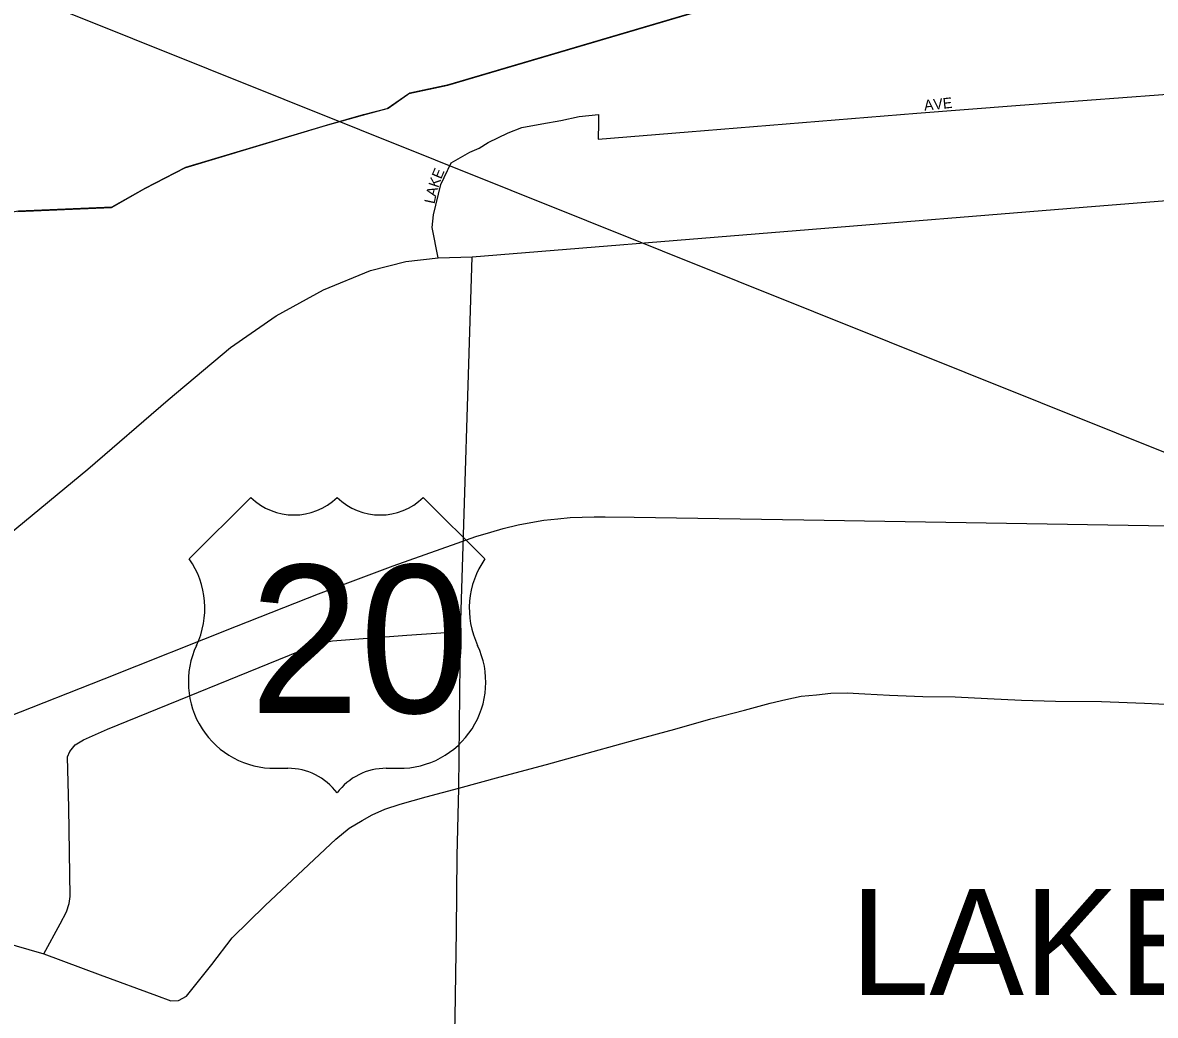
# Model space of a CAD drawing. Extents: x -561 to 1170, y 0 to 846.
# Drawn here: x 141.08 to 155.48, y 270.3 to 282.92 of the extents above; entities that cross this region are included whole.
import ezdxf

# ---------------------------------------------------------------- set-up
doc = ezdxf.new("R2010")
doc.units = 0
for name, color, linetype in [('GM_X_City_Street', 7, 'Continuous'), ('GM_X_City_Street_Text', 7, 'Continuous'), ('GM_X_Corporation_Text', 7, 'Continuous'), ('GM_X_County', 7, 'Continuous'), ('GM_X_Major_Lake', 7, 'Continuous'), ('GM_X_Rail_Line', 7, 'Continuous'), ('GM_X_State_Route', 7, 'Continuous'), ('GM_X_US_Location', 7, 'Continuous'), ('GM_X_US_Route', 7, 'Continuous'), ('GM_X_US_Shield', 7, 'Continuous'), ('SH_Text', 7, 'Continuous')]:
    doc.layers.add(name, color=color, linetype=linetype)

msp = doc.modelspace()

# ---------------------------------------------------------------- linework, layer by layer
at = {"layer": 'GM_X_City_Street'}
for points in [[(148.401, 281.709), (148.4, 281.649), (148.395, 281.44), (149.541, 281.533), (152.447, 281.77), (153.706, 281.868), (158.244, 282.207)], [(146.479, 281.042), (146.488, 281.061), (146.525, 281.139), (146.764, 281.274), (146.883, 281.327), (146.996, 281.397), (147.251, 281.52), (147.424, 281.59), (147.678, 281.638), (147.921, 281.68), (148.154, 281.728), (148.402, 281.754), (148.401, 281.709)], [(146.363, 279.933), (146.284, 280.318), (146.301, 280.48), (146.394, 280.864), (146.479, 281.042)]]:
    msp.add_lwpolyline(points, dxfattribs=at)
at = {"layer": 'GM_X_County'}
msp.add_lwpolyline([(141.015, 280.523), (142.205, 280.574), (142.632, 280.815), (143.139, 281.078), (144.928, 281.614), (145.398, 281.747), (145.712, 281.831), (145.987, 282.022), (146.484, 282.128), (153.359, 284.158)], dxfattribs=at)
at = {"layer": 'GM_X_Major_Lake'}
for points in [[(136.359, 279.012), (137.109, 279.037), (138.946, 279.764), (139.491, 280.049), (139.816, 280.148), (140.151, 280.205), (140.496, 280.445), (141.026, 280.53), (142.217, 280.581), (142.643, 280.822), (143.151, 281.085), (144.94, 281.621), (145.41, 281.754), (145.724, 281.837), (145.999, 282.029), (146.496, 282.135), (153.371, 284.165)], [(141.026, 280.53), (142.217, 280.581), (142.643, 280.822), (143.151, 281.085), (144.94, 281.621), (145.41, 281.754), (145.724, 281.837), (145.999, 282.029), (146.496, 282.135), (153.371, 284.165)]]:
    msp.add_lwpolyline(points, dxfattribs=at)
at = {"layer": 'GM_X_Rail_Line'}
msp.add_lwpolyline([(140.888, 274.096), (142.115, 274.579), (143.795, 275.246), (144.838, 275.657), (145.789, 276.015), (146.602, 276.304), (146.842, 276.386), (147.029, 276.443), (147.187, 276.489), (147.378, 276.535), (147.541, 276.567), (147.703, 276.594), (147.883, 276.614), (148.039, 276.628), (148.191, 276.635), (148.347, 276.639), (148.484, 276.638), (148.856, 276.634), (151.01, 276.6), (157.974, 276.485)], dxfattribs=at)
at = {"layer": 'GM_X_State_Route'}
msp.add_lwpolyline([(146.588, 269.463), (146.557, 269.475), (146.576, 270.27), (146.594, 271.374), (146.601, 272.327), (146.625, 273.187), (146.645, 275.179)], dxfattribs=at)
at = {"layer": 'GM_X_US_Route'}
for points in [[(146.793, 279.944), (154.72, 280.588), (158.229, 280.868), (163.988, 280.826), (165.715, 280.762), (171.059, 280.399), (171.619, 280.36), (175.976, 279.984), (176.373, 279.904), (176.91, 279.745), (186.607, 276.802)], [(140.904, 276.416), (141.904, 277.245), (142.928, 278.128), (143.72, 278.793), (144.301, 279.196), (144.901, 279.524), (145.502, 279.77), (145.948, 279.884), (146.363, 279.933), (146.793, 279.944)], [(146.645, 275.179), (146.793, 279.944)], [(141.552, 271.461), (141.634, 271.614), (141.667, 271.719), (141.681, 271.808), (141.664, 272.936), (141.648, 273.587), (141.678, 273.654), (141.745, 273.738), (141.85, 273.802), (142.154, 273.937), (144.72, 274.982), (144.866, 275.032), (145.018, 275.059), (145.964, 275.133), (146.645, 275.179)], [(142.778, 270.549), (142.962, 270.481), (143.058, 270.486), (143.16, 270.541), (143.483, 270.944), (143.743, 271.282), (144.159, 271.695), (145.059, 272.538), (145.231, 272.679), (145.393, 272.777), (145.523, 272.848), (145.685, 272.919), (145.88, 272.984), (146.209, 273.078), (146.625, 273.187), (147.15, 273.33), (147.739, 273.489), (148.334, 273.654), (148.885, 273.807), (149.372, 273.939), (149.831, 274.07), (150.258, 274.18), (150.582, 274.268), (150.782, 274.317), (150.977, 274.356), (151.172, 274.373), (151.356, 274.395), (151.561, 274.401), (151.788, 274.386), (152.102, 274.371), (152.524, 274.351), (152.936, 274.347), (153.347, 274.327), (153.78, 274.307), (154.213, 274.292), (154.797, 274.289), (155.343, 274.269), (155.89, 274.244)], [(139.859, 271.399), (140.021, 271.386), (140.803, 271.239), (141.347, 271.08)], [(141.347, 271.08), (141.552, 271.461)], [(141.347, 271.08), (142.063, 270.815)], [(142.063, 270.815), (142.778, 270.549)]]:
    msp.add_lwpolyline(points, dxfattribs=at)
at = {"layer": 'GM_X_US_Shield'}
for p, q in [((143.979, 276.886), (143.196, 276.103)), ((146.955, 276.103), (146.172, 276.886)), ((144.293, 273.44), (144.449, 273.44)), ((145.702, 273.44), (145.859, 273.44))]:
    msp.add_line(p, q, dxfattribs=at)
for centre, radius, start, end in [((144.527, 277.445), 0.783, 225.573, 314.427), ((145.624, 277.445), 0.783, 225.573, 314.427), ((142.298, 275.474), 1.096, 334.5471, 35.0009), ((147.853, 275.474), 1.096, 144.9991, 205.4529), ((144.28, 274.536), 1.096, 154.8319, 270.6383), ((145.871, 274.536), 1.096, 269.3617, 25.1681), ((144.449, 272.657), 0.783, 36.8699, 90), ((145.702, 272.657), 0.783, 90, 143.1301)]:
    msp.add_arc(centre, radius, start, end, dxfattribs=at)
at = {"layer": 'SH_Text'}
msp.add_lwpolyline([(129.942, 309.069), (200.26, 259.555), (129.942, 287.747)], close=True, dxfattribs=at)

# ---------------------------------------------------------------- texts
at = {"layer": 'GM_X_City_Street_Text'}
for s, rotation, p in [('AVE', 5.9105, (152.546, 281.803)), ('E', 67.3085, (146.399, 280.925)), ('K', 71.4779, (146.362, 280.815)), ('A', 75.6474, (146.333, 280.702)), ('L', 77.7321, (146.314, 280.611))]:
    msp.add_text(s, height=0.135, rotation=rotation, dxfattribs=at).set_placement(p)
at = {"layer": 'GM_X_Corporation_Text'}
msp.add_text('LAKEWOOD', height=1.35, rotation=0, dxfattribs=at).set_placement((151.604, 270.555))
at = {"layer": 'GM_X_US_Location'}
for s in ['/', '0']:
    msp.add_text(s, height=0.0027, dxfattribs=at).set_placement((145.075, 275.07))
msp.add_text('20', height=0.0027, rotation=0, dxfattribs=at).set_placement((144.517, 274.511))
at = {"layer": 'GM_X_US_Shield'}
msp.add_text('20', height=1.8795, dxfattribs=at).set_placement((143.964, 274.145))

doc.saveas('drawing.dxf')
